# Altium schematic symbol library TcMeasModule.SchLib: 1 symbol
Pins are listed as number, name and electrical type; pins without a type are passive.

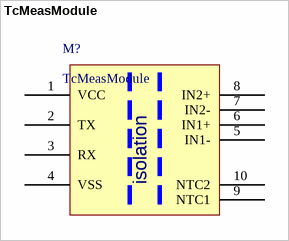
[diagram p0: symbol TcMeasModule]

## TcMeasModule
designator M?
2路隔离热电偶测量模块
pins: 1 VCC, 2 TX, 3 RX, 4 VSS, 5 IN1-, 6 IN1+, 7 IN2-, 8 IN2+, 9 NTC1, 10 NTC2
